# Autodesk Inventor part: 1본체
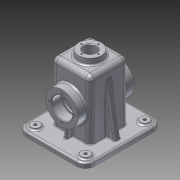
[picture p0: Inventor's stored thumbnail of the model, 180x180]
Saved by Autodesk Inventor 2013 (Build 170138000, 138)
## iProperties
Created: 2016-01
Part Number: 1본체
Material: 알루미늄 6061
Document SubType Name: Modeling
Designer: Administrator
Density: 2.71 g/cm^3
Mass: 849.35 g
Surface Area: 903.523 cm^2
Volume: 313.413 cm^3
Author: Administrator
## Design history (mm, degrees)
sketch "스케치1"
  geometry: L1 (-57.5, 65)-(57.5, 65); L2 (57.5, 65)-(57.5, -65); L3 (57.5, -65)-(-57.5, -65); L4 (-57.5, -65)-(-57.5, 65); 3 further points
  constraints: 8 end point, 2 midpoint, 2 parallel, 1 horizontal, 1 horizontal alignment, 1 perpendicular, 1 vertical alignment
  dimensions: "d0" = 115 distance of L2.end L3.end; "d2" = 130 distance of L1.end L2.end
extrude "돌출1" new body sketch "스케치1" distance "d3" = 8; taper "d4" = 0 deg
sketch "스케치2"
  geometry: L1 (-32.5, 32.5)-(32.5, 32.5); L2 (32.5, 32.5)-(32.5, -32.5); L3 (32.5, -32.5)-(-32.5, -32.5); L4 (-32.5, -32.5)-(-32.5, 32.5); 3 further points
  constraints: 8 end point, 2 midpoint, 2 parallel, 1 horizontal, 1 horizontal alignment, 1 perpendicular, 1 vertical alignment
  dimensions: "d5" = 65 distance of L1.end L2.end; "d7" = 65 distance of L2.end L3.end
extrude "돌출2" join sketch "스케치2" distance "d8" = 100; taper "d9" = 0 deg
fillet "모깎기1" dims "d10" = 15
sketch "스케치3"
  geometry: L1 (-57.5, 50)-(-57.5, -50) reference; L2 (-42.5, -65)-(42.5, -65) reference; L3 (57.5, -50)-(57.5, 50) reference; L4 (42.5, 65)-(-42.5, 65) reference; L5 (-42.5, 60)-(42.5, 60); L6 (52.5, 50)-(52.5, -50); L7 (42.5, -60)-(-42.5, -60); L8 (-52.5, -50)-(-52.5, 50); A1 r 15 centre (-42.5, 50) between (-42.5, 65) and (-57.5, 50) reference; A2 r 15 centre (-42.5, -50) between (-57.5, -50) and (-42.5, -65) reference; A3 r 15 centre (42.5, -50) between (42.5, -65) and (57.5, -50) reference; A4 r 15 centre (42.5, 50) between (57.5, 50) and (42.5, 65) reference; A5 r 10 centre (-42.5, 50) between (-42.5, 60) and (-52.5, 50); A6 r 10 centre (42.5, 50) between (52.5, 50) and (42.5, 60); A7 r 10 centre (42.5, -50) between (42.5, -60) and (52.5, -50); A8 r 10 centre (-42.5, -50) between (-52.5, -50) and (-42.5, -60); 1 further point
  constraints: 8 end point, 8 point on circle, 4 centre point, 7 other
  dimensions: "d11" = 5 distance between parallel lines of L1 L8
extrude "돌출3" join sketch "스케치3" distance "d12" = 2; taper "d13" = 0 deg
sketch "스케치6"
  geometry: C1 r 27.5 at (0, 55); 1 further point
  constraints: 1 centre point, 1 vertical alignment
  dimensions: "d24" = 55 diameter of C1; "d26" = 55 distance of point (0, 0) C1.centre
extrude "돌출6" join sketch "스케치6" stored distance "d27" = 95; taper "d28" = 0 deg
sketch "스케치4"
  geometry: L1 (27.5, 27.5)-(-27.5, 27.5); L2 (-27.5, 27.5)-(-27.5, -27.5); L3 (-27.5, -27.5)-(27.5, -27.5); L4 (27.5, -27.5)-(27.5, 27.5); L5 (27.5, 27.5)-(-27.5, -27.5); L6 (-27.5, 27.5)-(27.5, -27.5); 1 further point
  constraints: 12 end point, 2 midpoint, 2 parallel, 1 horizontal, 1 perpendicular
  dimensions: "d14" = 55 distance of L1.end L2.end; "d16" = 55 distance of L1.start L1.end
extrude "돌출4" cut sketch "스케치4" distance "d17" = 105; taper "d18" = 0 deg
sketch "스케치5"
  geometry: L1 (27.5, -2)-(-27.5, -2) reference; L2 (27.5, -2)-(27.5, 103) reference; L3 (27.5, 103)-(-27.5, 103) reference; L4 (-27.5, -2)-(-27.5, 103) reference; L5 (-32.5, 8)-(32.5, 8) reference; L6 (-27.5, 8)-(-42.5, 8); L7 (-42.5, 8)-(-42.5, 63); L8 (-42.5, 63)-(-27.5, 63); L9 (-27.5, 63)-(-27.5, 8); 1 further point
  constraints: 8 end point, 2 parallel, 2 point on line, 1 horizontal, 1 perpendicular
  dimensions: "d19" = 15 distance of L6.start L6.end; "d21" = 55 distance of L6.end L7.end
extrude "돌출5" join sketch "스케치5" stored distance "d22" = 6; taper "d23" = 0 deg
node "작업 평면1"
sketch "스케치7"
  geometry: C1 r 20 at (0, 0); 1 further point
  constraints: 1 centre point, 1 coincident
  dimensions: "d30" = 40 diameter of C1
extrude "돌출7" join sketch "스케치7" stored distance "d31" = 95; taper "d32" = 0 deg
feature "면 기울기1" dims angle "d104" = 5 deg
sketch "스케치8"
  geometry: C1 r 7.5 at (-42.5, 50); C2 r 7.5 at (42.5, 50); C3 r 7.5 at (42.5, -50); C4 r 7.5 at (-42.5, -50); A1 r 15 centre (42.5, 50) between (57.5, 50) and (42.5, 65) reference; A2 r 15 centre (-42.5, 50) between (-42.5, 65) and (-57.5, 50) reference; A3 r 15 centre (-42.5, -50) between (-57.5, -50) and (-42.5, -65) reference; A4 r 15 centre (42.5, -50) between (42.5, -65) and (57.5, -50) reference; 1 further point
  constraints: 4 centre point, 4 coincident
  dimensions: "d33" = 15 diameter of C1; "d34" = 15 diameter of C2; "d35" = 15 diameter of C3; "d36" = 15 diameter of C4
extrude "돌출8" join sketch "스케치8" distance "d37" = 3; taper "d38" = 0 deg
sketch "스케치9"
  geometry: C1 r 7.5 at (0, 0) reference; C2 r 7.5 at (-85, 0) reference; C3 r 7.5 at (-85, 100) reference; C4 r 7.5 at (0, 100) reference; 5 further points
  constraints: 4 coincident
hole "구멍1" sketch "스케치9" at (-85, 0), (-85, 100), (0, 100), (0, 0) diameter "d39" = 5; stored, may be unused: countersink angle "d43" = 90 deg, drill point angle "d45" = 118 deg; dims "d40" = 6, "d41" = 4, "d42" = 2, "d44" = 8
sketch "스케치10"
  geometry: C1 r 27.5 at (0, 0) reference; C2 r 15 at (0, 0); 1 further point
  constraints: 1 centre point, 1 coincident
  dimensions: "d46" = 30 diameter of C2
extrude "돌출9" cut sketch "스케치10" stored distance "d47" = 3; taper "d48" = 0 deg
sketch "스케치11"
  geometry: C1 r 20 at (0, 0) reference; C2 r 10.5 at (0, 0)
  constraints: 1 centre point, 1 coincident
  dimensions: "d49" = 21 diameter of C2
extrude "돌출10" cut sketch "스케치11" stored distance "d50" = 3; taper "d51" = 0 deg
sketch "스케치12"
  geometry: C1 r 15 at (0, 0) reference; C2 r 27.5 at (0, 0) reference; C3 r 17.5 at (0, 0); 1 further point
  constraints: 1 centre point, 1 coincident
  dimensions: "d53" = 35 diameter of C3
extrude "돌출11" cut sketch "스케치12" distance "d54" = 17; taper "d55" = 0 deg
sketch "스케치13"
  geometry: L1 (-47.5, 8)-(-30.787, 102.783); L2 (52.5, 0)-(52.5, -2) reference; L3 (52.5, -2)-(27.5, -2) reference; L4 (27.5, -2)-(27.5, 103) reference; L5 (27.5, 103)-(10.5, 103) reference; L6 (10.5, 103)-(10.5, 118) reference; L7 (10.5, 118)-(19.125, 118) reference; L8 (19.125, 118)-(20, 108) reference; L9 (20, 108)-(32.5, 108) reference; L10 (32.5, 108)-(32.5, 8) reference; L11 (32.5, 8)-(57.5, 8) reference; L12 (57.5, 8)-(57.5, 0) reference; L13 (57.5, 0)-(52.5, 0) reference; L14 (-52.5, -2)-(-52.5, 0) reference; L15 (-52.5, 0)-(-57.5, 0) reference; L16 (-57.5, 0)-(-57.5, 8) reference; L17 (-57.5, 8)-(-32.5, 8) reference; L18 (-32.5, 8)-(-32.5, 108) reference; L19 (-32.5, 108)-(-20, 108) reference; L20 (-20, 108)-(-19.125, 118) reference; L21 (-19.125, 118)-(-10.5, 118) reference; L22 (-10.5, 118)-(-10.5, 103) reference; L23 (-10.5, 103)-(-27.5, 103) reference; L24 (-27.5, 103)-(-27.5, -2) reference; L25 (-27.5, -2)-(-52.5, -2) reference; 2 further points
  constraints: 2 end point, 1 horizontal alignment, 1 midpoint
  dimensions: "d56" = 10 distance from line of L16 L1.start; "d57" = 10 deg angle of L16 L1
feature "리브1" sketch "스케치13" dims "d58" = 1, "d59" = 10, "d60" = 0, "d61" = 0, "d62" = 1, "d63" = 1
sketch "스케치14"
  geometry: C1 r 10.5 at (0, 0) reference; 1 further point
  constraints: 1 horizontal alignment
  dimensions: "d64" = 14.5 distance of point (-14.5, 0) C1.centre
hole "구멍2" sketch "스케치14" at (-14.5, 0) diameter "d65" = 2.459; stored, may be unused: countersink angle "d69" = 90 deg, drill point angle "d71" = 118 deg; dims "d66" = 7, "d67" = 4, "d68" = 2, "d70" = 9
sketch "스케치15"
  geometry: C1 r 17.5 at (0, 0) reference; 2 further points
  constraints: 1 vertical alignment
  dimensions: "d75" = 21 distance of C1.centre point (0, 21)
hole "구멍3" sketch "스케치15" at (0, 21) diameter "d76" = 3.242; stored, may be unused: countersink angle "d80" = 90 deg, drill point angle "d82" = 118 deg; dims "d77" = 8, "d78" = 4, "d79" = 2, "d81" = 10
fillet "모깎기2" dims "d86" = 8
fillet "모깎기3" dims "d87" = 8
fillet "모깎기4" dims "d88" = 0.3
fillet "모깎기5" dims "d89" = 3
fillet "모깎기6" dims "d90" = 3
fillet "모깎기7" dims "d91" = 3
fillet "모깎기8" dims "d92" = 3
fillet "모깎기9" dims "d93" = 1
fillet "모깎기10" dims "d94" = 3
fillet "모깎기11" dims "d95" = 3
chamfer "모따기1" distance "d96" = 1; stored, may be unused: second distance "d97" = 2, angle "d98" = 45 deg
fillet "모깎기12" dims "d99" = 3
fillet "모깎기13" dims "d100" = 3
sketch "스케치16"
  geometry: L1 (43.625, -18)-(5.375, -18) reference; A1 r 30.5 centre (24.5, 45) between (0, 26.834) and (49, 26.834) reference; 2 further points
  constraints: 1 vertical alignment, 1 other
  dimensions: "d101" = 27 distance from line of point (24.5, 9) L1
feature "엠보싱1" sketch "스케치16" dims "d102" = 0.5, "d103" = 0
node "솔리드1"
mirror "대칭1"
mirror "대칭2"
mirror "대칭3"
pattern_circular "원형 패턴1" dims angle "d73" = 360 deg
pattern_circular "원형 패턴2" dims angle "d84" = 360 deg
mirror "대칭4"
node "투영된 루프1"
node "투영된 루프2"
node "투영된 루프3"
node "투영된 루프4"
node "절단 모서리 투영1"
other parameters: "d29" = 118
